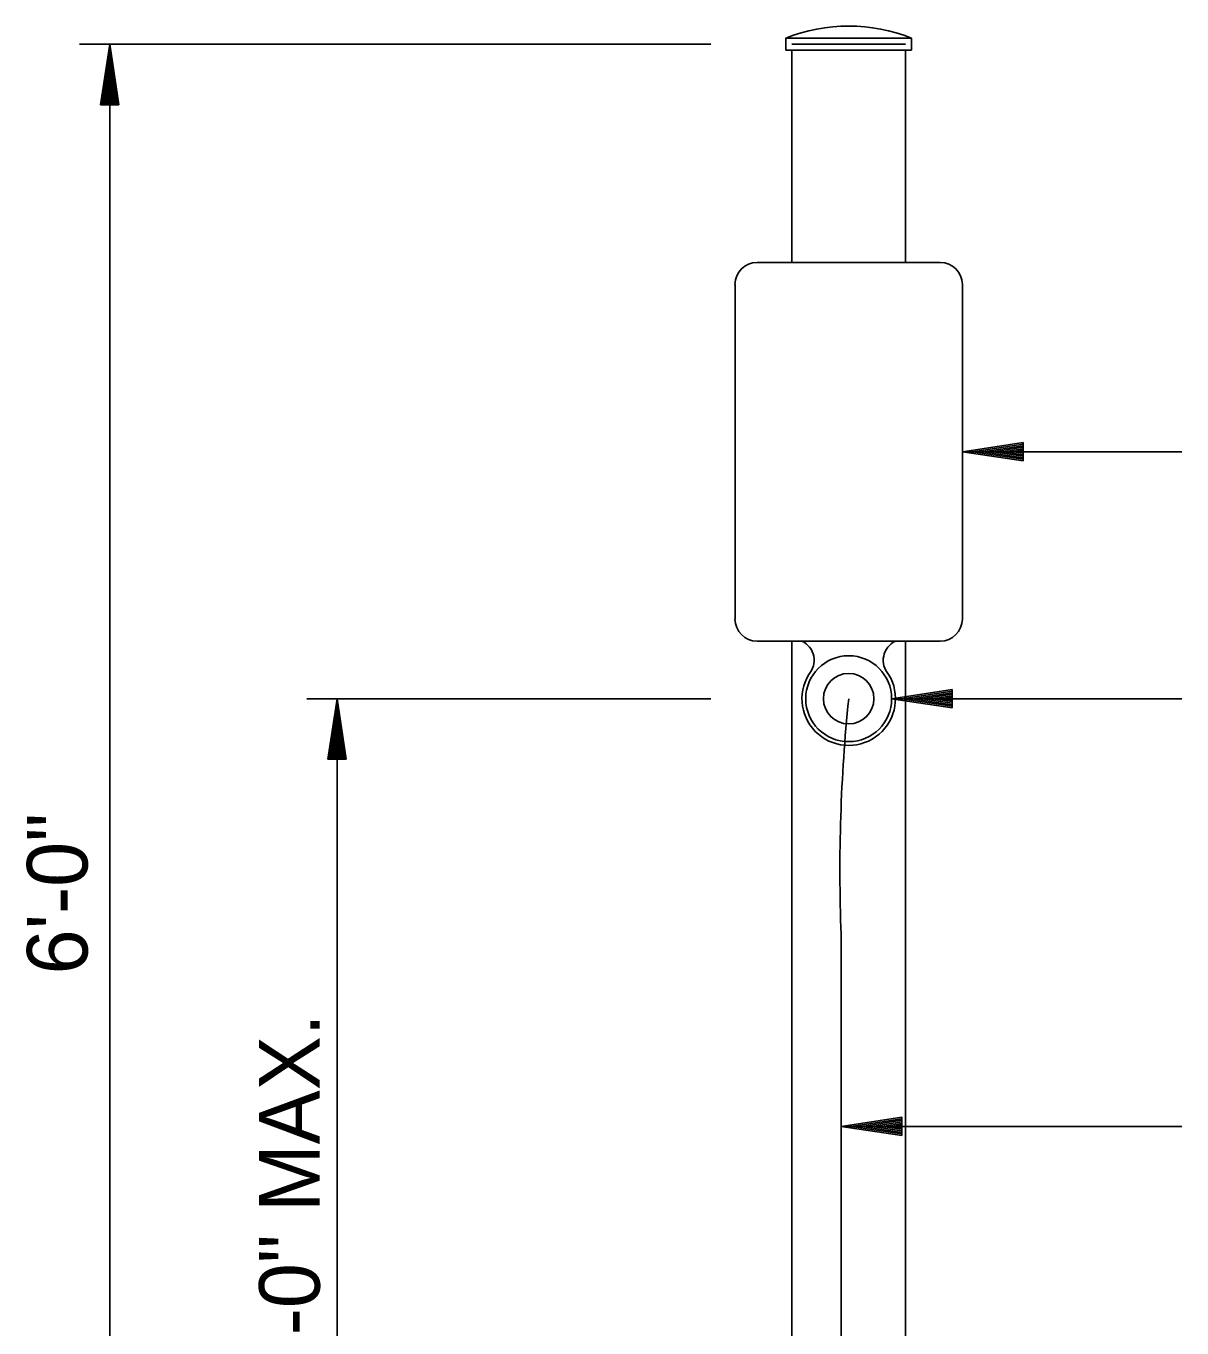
# Model space of a CAD drawing. Extents: x 418532 to 420296, y -565948 to -565286.
# Drawn here: x 418912.3 to 418998.1, y -565388.6 to -565291.9 of the extents above; entities that cross this region are included whole.
import ezdxf

# ---------------------------------------------------------------- set-up
doc = ezdxf.new("R2010")
doc.units = 0
doc.layers.add('R_Draft', color=7, linetype='Continuous')

msp = doc.modelspace()

# ---------------------------------------------------------------- linework, layer by layer
at = {"layer": 'R_Draft'}
for p, q in [((418978.037, -565292.781), (418968.699, -565292.781)), ((418968.699, -565293.681), (418968.699, -565292.781)), ((418978.037, -565293.681), (418978.037, -565292.781)), ((418916.274, -565293.231), (418963.131, -565293.231)), ((418917.849, -565297.731), (418918.524, -565293.231)), ((418918.524, -565431.827), (418918.524, -565293.231)), ((418919.199, -565297.731), (418918.524, -565293.231)), ((418978.037, -565293.681), (418968.699, -565293.681)), ((418977.587, -565293.231), (418969.149, -565293.231)), ((418969.149, -565309.427), (418969.149, -565293.681)), ((418977.587, -565309.427), (418977.587, -565293.681)), ((418917.962, -565297.731), (418918.524, -565293.983)), ((418918.077, -565297.731), (418918.524, -565294.757)), ((418919.087, -565297.731), (418918.524, -565293.983)), ((418918.972, -565297.731), (418918.524, -565294.757)), ((418918.189, -565297.731), (418918.524, -565295.506)), ((418918.86, -565297.731), (418918.524, -565295.506)), ((418918.306, -565297.731), (418918.524, -565296.269)), ((418918.745, -565297.731), (418918.524, -565296.269)), ((418918.419, -565297.731), (418918.524, -565297.02)), ((418918.63, -565297.731), (418918.524, -565297.02)), ((418917.849, -565297.731), (418919.199, -565297.731)), ((418966.571, -565309.427), (418980.165, -565309.427)), ((418964.931, -565311.068), (418964.931, -565335.912)), ((418981.806, -565311.068), (418981.806, -565335.912)), ((418986.306, -565322.815), (418981.806, -565323.49)), ((418981.806, -565323.49), (418998.099, -565323.49)), ((418986.306, -565324.165), (418981.806, -565323.49)), ((418986.306, -565322.927), (418982.557, -565323.49)), ((418986.306, -565324.052), (418982.557, -565323.49)), ((418986.306, -565323.042), (418983.331, -565323.49)), ((418986.306, -565323.938), (418983.331, -565323.49)), ((418986.306, -565323.155), (418984.08, -565323.49)), ((418986.306, -565323.825), (418984.08, -565323.49)), ((418986.306, -565323.269), (418984.843, -565323.49)), ((418986.306, -565323.708), (418984.843, -565323.49)), ((418986.306, -565323.384), (418985.595, -565323.49)), ((418986.306, -565323.596), (418985.595, -565323.49)), ((418986.306, -565324.165), (418986.306, -565322.815)), ((418966.571, -565337.552), (418980.165, -565337.552)), ((418969.149, -565428.231), (418969.149, -565337.552)), ((418977.587, -565428.231), (418977.587, -565337.552)), ((418981.056, -565341.152), (418976.556, -565341.827)), ((418981.056, -565342.502), (418981.056, -565341.152)), ((418933.149, -565341.827), (418963.131, -565341.827)), ((418934.724, -565346.327), (418935.399, -565341.827)), ((418935.399, -565431.827), (418935.399, -565341.827)), ((418936.074, -565346.327), (418935.399, -565341.827)), ((418976.556, -565341.827), (418998.099, -565341.827)), ((418981.056, -565342.502), (418976.556, -565341.827)), ((418981.056, -565341.265), (418977.307, -565341.827)), ((418981.056, -565342.39), (418977.307, -565341.827)), ((418981.056, -565341.38), (418978.081, -565341.827)), ((418981.056, -565342.275), (418978.081, -565341.827)), ((418981.056, -565341.492), (418978.83, -565341.827)), ((418981.056, -565342.163), (418978.83, -565341.827)), ((418981.056, -565341.607), (418979.593, -565341.827)), ((418981.056, -565342.046), (418979.593, -565341.827)), ((418981.056, -565341.722), (418980.345, -565341.827)), ((418981.056, -565341.933), (418980.345, -565341.827)), ((418934.837, -565346.327), (418935.399, -565342.579)), ((418935.962, -565346.327), (418935.399, -565342.579)), ((418934.952, -565346.327), (418935.399, -565343.353)), ((418935.847, -565346.327), (418935.399, -565343.353)), ((418935.064, -565346.327), (418935.399, -565344.102)), ((418935.181, -565346.327), (418935.399, -565344.865)), ((418935.735, -565346.327), (418935.399, -565344.102)), ((418935.62, -565346.327), (418935.399, -565344.865)), ((418935.294, -565346.327), (418935.399, -565345.616)), ((418935.505, -565346.327), (418935.399, -565345.616)), ((418934.724, -565346.327), (418936.074, -565346.327)), ((418972.806, -565458.283), (418972.806, -565359.332)), ((418977.311, -565372.907), (418972.811, -565373.582)), ((418977.311, -565373.02), (418973.562, -565373.582)), ((418977.311, -565374.257), (418977.311, -565372.907)), ((418972.811, -565373.582), (418998.099, -565373.582)), ((418977.311, -565374.257), (418972.811, -565373.582)), ((418977.311, -565374.145), (418973.562, -565373.582)), ((418977.311, -565373.134), (418974.336, -565373.582)), ((418977.311, -565374.03), (418974.336, -565373.582)), ((418977.311, -565373.247), (418975.085, -565373.582)), ((418977.311, -565373.917), (418975.085, -565373.582)), ((418977.311, -565373.362), (418975.848, -565373.582)), ((418977.311, -565373.8), (418975.848, -565373.582)), ((418977.311, -565373.476), (418976.6, -565373.582)), ((418977.311, -565373.688), (418976.6, -565373.582))]:
    msp.add_line(p, q, dxfattribs=at)
for radius in [3.187, 1.875]:
    msp.add_circle((418973.368, -565341.827), radius, dxfattribs=at)
for centre, radius, start, end in [((418973.368, -565304.441), 12.56, 68.17774, 111.82226), ((418966.571, -565311.068), 1.641, 90, 180), ((418980.165, -565311.068), 1.641, 0, 90), ((418966.571, -565335.912), 1.641, 180, 270), ((418980.165, -565335.912), 1.641, 270, 0), ((418969.229, -565338.977), 1.575, 318.19721, 64.80442), ((418977.507, -565338.977), 1.575, 115.19558, 221.80279), ((418973.368, -565341.827), 3.469, 148.74024, 31.25976), ((419097.181, -565354.567), 124.466, 174.12507, 182.19393)]:
    msp.add_arc(centre, radius, start, end, dxfattribs=at)

# ---------------------------------------------------------------- texts
for s, height, p in [('6\'-0"', 4.5, (418916.885, -565362.299)), ('3\'-6" MIN. - 4\'-0" MAX.', 4.49999, (418934.114, -565425.287))]:
    msp.add_text(s, height=height, rotation=90, dxfattribs=at).set_placement(p)

doc.saveas('drawing.dxf')
